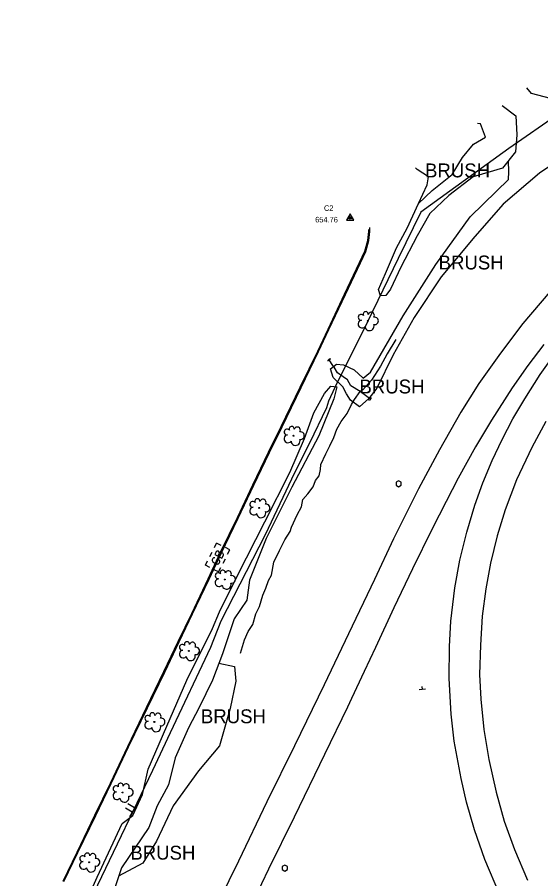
# Model space of a CAD drawing. Extents: x 2129547 to 2134906, y 657330 to 659734.
# Drawn here: x 2131710.5 to 2131974.2, y 658719.3 to 659153.2 of the extents above; entities that cross this region are included whole.
import ezdxf

# ---------------------------------------------------------------- set-up
doc = ezdxf.new("R2010")
doc.units = 0
for name, color, linetype in [('Default', 7, 'Continuous'), ('DR_X_Cells', 7, 'Continuous'), ('DR_X_Culvert', 7, 'Continuous'), ('HY_X_Water_Edge', 7, 'Continuous'), ('PM_X_Edge_Line', 7, 'Continuous'), ('PV_X_Curb', 7, 'Continuous'), ('PV_X_Parking_Lot', 7, 'Continuous'), ('RD_X_Cells', 7, 'Continuous'), ('RD_X_Fence', 7, 'Continuous'), ('SN_X_Public', 7, 'Continuous'), ('SV_P_Aerial_Targets', 7, 'Continuous'), ('VG_X_Cells', 7, 'Continuous'), ('VG_X_Shrub_Line_Lt', 7, 'Continuous'), ('VG_X_Text', 7, 'Continuous'), ('VG_X_Tree_Line_Lt', 7, 'Continuous')]:
    doc.layers.add(name, color=color, linetype=linetype)

# ---------------------------------------------------------------- blocks, each defined once
blk = doc.blocks.new('CULVERT')
at = {"layer": 'Default'}
blk.add_lwpolyline([(-0.0508, 0.1143), (0, 0.0635), (0, -0.0635), (-0.0508, -0.1143)], dxfattribs=at)
blk = doc.blocks.new('FCTRL')
at = {"layer": 'SV_P_Aerial_Targets'}
blk.add_lwpolyline([(-0.0229, -0.0147), (0.0229, -0.0147), (0, 0.0262)], close=True, dxfattribs=at)
for radius in [0.00889, 0.00203]:
    blk.add_circle((0, 0), radius, dxfattribs=at)
blk = doc.blocks.new('POST')
at = {"layer": 'RD_X_Cells'}
blk.add_lwpolyline([(-0.0165, -0.0095), (0, -0.019), (0.0165, -0.0095), (0.0165, 0.0095), (0, 0.019), (-0.0165, 0.0095), (-0.0165, -0.0095)], dxfattribs=at)
blk = doc.blocks.new('SGN1P')
at = {"layer": 'SN_X_Public'}
for p, q in [((0, 0), (-0.02032, 0)), ((0, 0.02032), (0, -0.02032))]:
    blk.add_line(p, q, dxfattribs=at)
blk = doc.blocks.new('POINT_DISPLAY')
at = {"layer": 'Default'}
blk.add_line((0, 0), (0, 0), dxfattribs=at)
blk = doc.blocks.new('SGN2P')
at = {"layer": 'Default'}
for p, q in [((0, 0.0061), (-0.0203, 0.0061)), ((0, 0.0203), (0, -0.0203)), ((0, -0.0061), (-0.0203, -0.0061))]:
    blk.add_line(p, q, dxfattribs=at)
blk.add_blockref('POINT_DISPLAY', (0, 0), dxfattribs=at)
blk = doc.blocks.new('TREE')
at = {"layer": 'VG_X_Cells'}
blk.add_circle((0, 0), 0.00305, dxfattribs=at)
for centre, radius, start, end in [((-0.0125, 0.0428), 0.0167, 354.0047, 205.9741), ((0.0232, 0.0359), 0.0197, 323.83, 165.0376), ((-0.0362, -0.0197), 0.0251, 96.1722, 320.5737), ((-0.042, 0.0237), 0.0187, 39.0625, 279.5412), ((0.0439, 0.0005), 0.0243, 259.1453, 101.4596), ((0.012, -0.0331), 0.029, 184.9476, 19.4572)]:
    blk.add_arc(centre, radius, start, end, dxfattribs=at)
blk = doc.blocks.new('GCB-X')
at = {"layer": 'Default'}
for p, q in [((-0.0317, 0.019), (-0.019, 0.019)), ((-0.0317, 0.0063), (-0.0317, 0.019)), ((-0.0063, 0.019), (0.0063, 0.019)), ((0.0034, 0.0007), (0.0124, 0.0007)), ((0.019, 0.019), (0.0317, 0.019)), ((0.0317, 0.0063), (0.0317, 0.019)), ((-0.0317, -0.019), (-0.0317, -0.0063)), ((-0.0317, -0.019), (-0.019, -0.019)), ((-0.0063, -0.019), (0.0063, -0.019)), ((0.019, -0.019), (0.0317, -0.019)), ((0.0317, -0.019), (0.0317, -0.0063))]:
    blk.add_line(p, q, dxfattribs=at)
blk.add_lwpolyline([(0.0116, 0.0099), (0.0034, 0.0099), (0.0034, -0.0104), (0.0124, -0.0104)], dxfattribs=at)
for centre, radius, start, end in [((0.0071, 0), 0.0233, 164.8107, 195.1893), ((-0.0094, 0.0037), 0.00645, 21.5603, 158.4397), ((0.0101, 0.0051), 0.00501, 296.8207, 73.0013), ((0.0101, -0.0049), 0.00597, 292.0547, 67.9453), ((-0.0094, -0.0037), 0.00645, 201.5603, 338.4397)]:
    blk.add_arc(centre, radius, start, end, dxfattribs=at)
for p in [(0, 0.019), (0, 0.019), (-0.0317, 0), (0, 0), (0, 0), (0, 0), (0, -0.019), (0, -0.019), (0.0317, 0)]:
    blk.add_blockref('POINT_DISPLAY', p, dxfattribs=at)

msp = doc.modelspace()

# ---------------------------------------------------------------- linework, layer by layer
at = {"layer": 'HY_X_Water_Edge'}
msp.add_line((2131887.97, 658961.17), (2131883.2, 658964.65), dxfattribs=at)
for points in [[(2131901.17, 658990.95), (2131896.86, 658983.63), (2131893.47, 658977.4), (2131888.89, 658970.44), (2131884.53, 658965.54), (2131883.2, 658964.65)], [(2131883.2, 658964.65), (2131878.51, 658967.61), (2131876.87, 658970.55), (2131874.64, 658972.14), (2131871.69, 658974.05), (2131870.08, 658976.97), (2131869.48, 658977.84), (2131867.59, 658980.58)], [(2131822.89, 658832.83), (2131824.9, 658839.58), (2131826.8, 658843.84), (2131829.18, 658847.35), (2131830.68, 658852.73), (2131832.47, 658856.4), (2131834.12, 658862.1), (2131835.62, 658865.7), (2131837.07, 658869.5), (2131838.56, 658872.24), (2131839.72, 658878.73), (2131842.52, 658884.57), (2131845.2, 658890.02), (2131847.97, 658894.15), (2131848.53, 658896.29), (2131851.48, 658902.57), (2131853.61, 658906.64), (2131854.26, 658910.37), (2131856.85, 658913.11), (2131859.46, 658916.75), (2131860.76, 658919.9), (2131862.51, 658922.2), (2131863.13, 658925.42), (2131863.3, 658928), (2131865.84, 658933.33), (2131867.85, 658937.29), (2131869.93, 658941.53), (2131871.51, 658945.66), (2131873.6, 658949.57), (2131876.63, 658953.65), (2131878.88, 658958.17), (2131880.28, 658960.6), (2131883.2, 658964.65)]]:
    msp.add_lwpolyline(points, dxfattribs=at)
at = {"layer": 'PM_X_Edge_Line'}
for points in [[(2131978.75, 659014.89), (2131965.12, 658998.99), (2131953.82, 658984.07), (2131943.04, 658968.64), (2131933.97, 658954.34), (2131923.09, 658935.26), (2131912.49, 658915.63), (2131899.96, 658890.48), (2131890.33, 658870.05), (2131877.31, 658842.67), (2131865.02, 658817), (2131850.13, 658786.31), (2131836.26, 658757.99), (2131821.92, 658728.21), (2131812.17, 658708.26)], [(2131975.74, 658988.36), (2131967.68, 658977.75), (2131959.69, 658966.5), (2131949.37, 658950.26), (2131941.23, 658936.89), (2131932.58, 658921.05), (2131926.43, 658909.25), (2131919.43, 658895.46), (2131909.58, 658875.42), (2131900.07, 658855.71), (2131890.97, 658835.8), (2131885.15, 658823.72), (2131878.85, 658809.99), (2131876.85, 658805.71), (2131865.23, 658781.92), (2131850, 658750.39), (2131837.03, 658724.06), (2131822.87, 658694.59)], [(2131953.58, 658711.22), (2131945.99, 658729.03), (2131940.74, 658743.97), (2131936.79, 658757.84), (2131933.98, 658769.81), (2131930.54, 658788.57), (2131929.04, 658802.17), (2131928.06, 658820.11), (2131928.17, 658836.26), (2131928.89, 658849.1), (2131930.82, 658865.76), (2131933.44, 658879.74), (2131936.95, 658893.82), (2131940.93, 658907.51), (2131944.89, 658918.75), (2131949.64, 658929.91), (2131954.68, 658940.5), (2131960.03, 658950.92), (2131966.1, 658961.01), (2131973.8, 658973.32), (2131982.78, 658985.7)], [(2131976.72, 658949.61), (2131969.57, 658936.5), (2131962.01, 658920.13), (2131956.26, 658905.17), (2131952.15, 658892.06), (2131948.8, 658878.24), (2131946.4, 658865.34), (2131944.62, 658851.53), (2131943.77, 658836.95), (2131943.35, 658822.22), (2131943.92, 658809.76), (2131945.44, 658794.5), (2131947.94, 658779.29), (2131951.61, 658762.97), (2131955.77, 658748.27), (2131960.9, 658734.03), (2131967.4, 658718.55)]]:
    msp.add_lwpolyline(points, dxfattribs=at)
at = {"layer": 'PV_X_Curb'}
msp.add_lwpolyline([(2131734.02, 658717.93), (2131741.05, 658732.51), (2131750.01, 658751.14), (2131757.83, 658767.24), (2131766.57, 658785.67), (2131776.02, 658805.3), (2131784.73, 658823.4), (2131792.02, 658838.58), (2131798.78, 658852.71), (2131807.09, 658870.14), (2131813.37, 658883.49), (2131821.79, 658900.94), (2131829.65, 658917.48), (2131837.53, 658933.99), (2131843.89, 658946.91), (2131853.44, 658966.7), (2131862.26, 658984.8), (2131867.47, 658995.95), (2131875.8, 659013.52), (2131883.34, 659029.45), (2131886.05, 659035.19), (2131887.57, 659040.67), (2131887.98, 659045.29), (2131888.01, 659047.27)], dxfattribs=at)
at = {"layer": 'PV_X_Parking_Lot'}
msp.add_lwpolyline([(2131733.57, 658718.15), (2131740.6, 658732.73), (2131749.56, 658751.36), (2131757.38, 658767.45), (2131766.12, 658785.88), (2131775.57, 658805.52), (2131784.28, 658823.61), (2131791.57, 658838.79), (2131798.33, 658852.92), (2131806.64, 658870.35), (2131812.92, 658883.7), (2131821.34, 658901.15), (2131829.19, 658917.7), (2131837.08, 658934.21), (2131843.44, 658947.13), (2131852.99, 658966.92), (2131861.81, 658985.02), (2131867.02, 658996.16), (2131875.35, 659013.74), (2131882.89, 659029.67), (2131885.58, 659035.37), (2131887.07, 659040.76), (2131887.48, 659045.31), (2131887.49, 659046.22)], dxfattribs=at)
at = {"layer": 'RD_X_Fence'}
msp.add_lwpolyline([(2132063.89, 659153.18), (2132044.02, 659147.7), (2132017.02, 659128.3), (2131983.81, 659104.8), (2131958.11, 659087.15), (2131928.28, 659065.59), (2131913.76, 659055.03), (2131902.3, 659031.68), (2131886.87, 658999.73), (2131870.43, 658966.66), (2131867.28, 658959.81), (2131866.21, 658956.4), (2131857.66, 658938.59), (2131850.11, 658923.77), (2131835.3, 658892.55), (2131813.09, 658849.05), (2131807.77, 658835.77), (2131787.53, 658792.78), (2131778.55, 658773.77), (2131750.93, 658716), (2131727.2, 658667.49), (2131715.31, 658642.03), (2131710.47, 658636.49)], dxfattribs=at)
at = {"layer": 'VG_X_Shrub_Line_Lt'}
for points in [[(2131987.99, 659084.42), (2131973.5, 659074.57), (2131955.14, 659058.97), (2131941.02, 659042.81), (2131924.01, 659022.5), (2131910.46, 659001.88), (2131899.87, 658983.14), (2131891.58, 658966.45), (2131887.54, 658961.16), (2131882.82, 658957.01), (2131878.35, 658960.25), (2131876.32, 658963.49), (2131874.45, 658967.03), (2131869.6, 658971.72), (2131868.29, 658976.17), (2131871.27, 658978.52), (2131874.78, 658978.19), (2131880.19, 658975.53), (2131884.75, 658971.43), (2131888.43, 658974.43), (2131904.81, 659002.86), (2131921.32, 659028.58), (2131938.63, 659052.7), (2131951.81, 659065.6), (2131957.93, 659071.5), (2131958.02, 659075.4), (2131957.9, 659080.85)], [(2131912.58, 659059.4), (2131916.96, 659068.83), (2131917.67, 659072.74), (2131911.87, 659076.44), (2131911.11, 659077.26)], [(2131812.04, 658827.87), (2131819.88, 658826.2), (2131820.49, 658818.72), (2131817.64, 658804.98), (2131812.3, 658786.22), (2131801.83, 658773.67), (2131789, 658756.05), (2131780.53, 658738.14), (2131773.77, 658727.16), (2131761.53, 658720.56)]]:
    msp.add_lwpolyline(points, dxfattribs=at)
at = {"layer": 'VG_X_Tree_Line_Lt'}
for points in [[(2131982.24, 659111.37), (2131969.49, 659114.84), (2131967.07, 659117.6)], [(2131954.71, 659108.7), (2131961.63, 659103.46), (2131962.12, 659094), (2131961.5, 659085.31), (2131954.95, 659077.2), (2131940.09, 659072.82), (2131927.89, 659063.34), (2131918.34, 659054.4), (2131911.89, 659043.06), (2131903.75, 659027.35), (2131898.41, 659016.17), (2131896.06, 659013.09), (2131893.37, 659012.8), (2131892.35, 659016.1), (2131895.89, 659024.18)], [(2131895.89, 659024.18), (2131901.56, 659036.98), (2131906.81, 659046.9), (2131912.58, 659059.4), (2131919.45, 659065.94), (2131929.56, 659073.95), (2131934.65, 659082.55), (2131940.35, 659089.26), (2131946.27, 659092.83), (2131943.77, 659099.49), (2131942.21, 659099.69)], [(2131738.81, 658693.27), (2131750.79, 658720.17), (2131763.3, 658747.2), (2131768.66, 658751.19), (2131773.5, 658761.67), (2131776.39, 658774.44), (2131785.82, 658796.1), (2131795.84, 658819.38), (2131808.75, 658845.26), (2131812.37, 658853.74), (2131821.46, 658871.96), (2131835.15, 658899.07), (2131847.72, 658923.91), (2131855.18, 658941.1), (2131859.93, 658953.95), (2131865.2, 658963.72), (2131868.4, 658967.44), (2131871.42, 658967.08), (2131869.99, 658960.92), (2131862.33, 658942.42), (2131848.77, 658916.46), (2131835.85, 658890.65), (2131827.37, 658869.75), (2131826.11, 658859.59), (2131819.81, 658850.2), (2131813.79, 658832.52), (2131808.76, 658819.23), (2131802.09, 658805.49), (2131796.68, 658795.37), (2131790.09, 658780.25), (2131786.69, 658766.6), (2131780.97, 658755.98), (2131776.75, 658745.1), (2131762.93, 658724.8), (2131757.42, 658708.18)]]:
    msp.add_lwpolyline(points, dxfattribs=at)

# ---------------------------------------------------------------- block references
at = {"layer": 'DR_X_Cells', "xscale": 196.8500000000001, "yscale": 196.85000000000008, "rotation": 63.162369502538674}
msp.add_blockref('GCB-X', (2131811.39, 658881.05), dxfattribs=at)
at = {"layer": 'DR_X_Culvert', "xscale": 7.8740000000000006}
for p, yscale, rotation in [((2131867.43, 658980.81), 7.874000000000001, 131.8818056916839), ((2131888.22, 658960.77), 7.8740000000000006, -42.5150880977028)]:
    msp.add_blockref('CULVERT', p, dxfattribs=dict(at, yscale=yscale, rotation=rotation))
at = {"layer": 'RD_X_Cells', "xscale": 78.74000000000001, "yscale": 78.74000000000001}
for p in [(2131902.56, 658918.22), (2131845.28, 658724.67)]:
    msp.add_blockref('POST', p, dxfattribs=at)
at = {"layer": 'SN_X_Public'}
for name, p, xscale, yscale, rotation in [('SGN1P', (2131914.52, 658814.59), 78.74000000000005, 78.74000000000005, -86.44702914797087), ('SGN2P', (2131769.02, 658753.95), 196.85000000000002, 196.85000000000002, -29.594920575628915)]:
    msp.add_blockref(name, p, dxfattribs=dict(at, xscale=xscale, yscale=yscale, rotation=rotation))
at = {"layer": 'SV_P_Aerial_Targets', "xscale": 78.74000000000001, "yscale": 78.74000000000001}
msp.add_blockref('FCTRL', (2131878.18, 659052.1), dxfattribs=at)
at = {"layer": 'VG_X_Cells', "xscale": 78.74000000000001, "yscale": 78.74000000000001}
for p in [(2131886.97, 659000.23), (2131849.69, 658942.43), (2131832.39, 658906.03), (2131814.96, 658870.01), (2131796.93, 658834.02), (2131779.52, 658798.25), (2131763.53, 658762.73), (2131746.71, 658727.57)]:
    msp.add_blockref('TREE', p, dxfattribs=at)

# ---------------------------------------------------------------- texts
at = {"layer": 'SV_P_Aerial_Targets'}
for s, p in [('C2', (2131864.97, 659055.67)), ('654.76', (2131860.51, 659049.84))]:
    msp.add_text(s, height=2.8, dxfattribs=at).set_placement(p)
at = {"layer": 'VG_X_Text'}
for p in [(2131915.85, 659072.52), (2131922.7, 659026.15), (2131882.82, 658963.7), (2131802.97, 658797.61), (2131767.43, 658728.91)]:
    msp.add_text('BRUSH', height=7, dxfattribs=at).set_placement(p)

doc.saveas('drawing.dxf')
